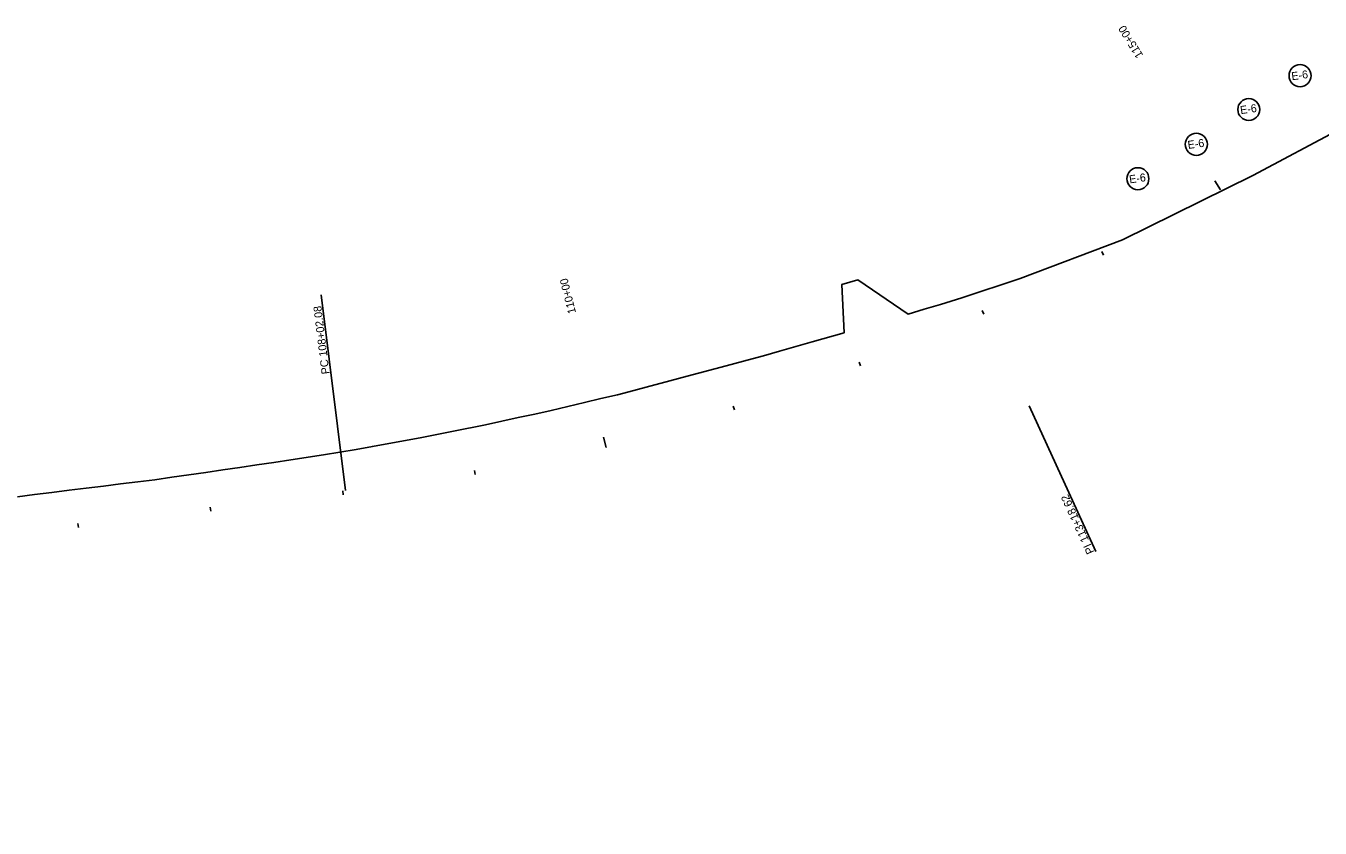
# Model space of a CAD drawing. Extents: x 1568908 to 1572777, y 730965 to 733090.
# Drawn here: x 1570843 to 1571813, y 732028 to 732629 of the extents above; entities that cross this region are included whole.
import ezdxf

# ---------------------------------------------------------------- set-up
doc = ezdxf.new("R2010")
doc.units = 0
for name, color, linetype in [('R_Erosion', 7, 'Continuous'), ('R_Horz Alg Annot', 7, 'Continuous'), ('R_No Plot', 7, 'Continuous')]:
    doc.layers.add(name, color=color, linetype=linetype)

msp = doc.modelspace()

# ---------------------------------------------------------------- linework, layer by layer
at = {"layer": 'R_Erosion'}
for centre in [(1571798.16, 732591.48), (1571759.71, 732566.13), (1571720.36, 732540.04), (1571676.53, 732514.23)]:
    msp.add_circle(centre, 8.26, dxfattribs=at)
at = {"layer": 'R_Horz Alg Annot'}
for points in [[(1571734.19, 732512.66), (1571738.37, 732505.84)], [(1571650.86, 732457.02), (1571649.45, 732459.67)], [(1571082.41, 732280.73), (1571064.28, 732427.34)], [(1571561, 732412.75), (1571559.76, 732415.48)], [(1571468.61, 732374.05), (1571467.54, 732376.85)], [(1571374.03, 732341.07), (1571373.13, 732343.93)], [(1571595.05, 732344.13), (1571644.93, 732234.99)], [(1571275.93, 732320.71), (1571277.86, 732312.94)], [(1571179.72, 732292.7), (1571179.18, 732295.65)], [(1571080.72, 732277.5), (1571080.35, 732280.48)], [(1570981.47, 732265.23), (1570981.1, 732268.21)], [(1570882.23, 732252.95), (1570881.86, 732255.93)]]:
    msp.add_lwpolyline(points, dxfattribs=at)
at = {"layer": 'R_No Plot'}
for points in [[(1572777.39, 731519.96), (1571905.83, 732616.57), (1571828.51, 732551.75), (1571762.8, 732516.69), (1571664.98, 732468.4), (1571588.26, 732439.45), (1571544.6, 732425.09)], [(1572777.39, 731519.96), (1571905.83, 732616.57), (1571828.51, 732551.75), (1571762.8, 732516.69), (1571664.98, 732468.4), (1571588.26, 732439.45), (1571544.6, 732425.09)], [(1572777.39, 731519.96), (1571905.83, 732616.57), (1571828.51, 732551.75), (1571762.8, 732516.69), (1571664.98, 732468.4), (1571588.26, 732439.45), (1571544.6, 732425.09)], [(1572777.39, 731519.96), (1571905.83, 732616.57), (1571828.51, 732551.75), (1571762.8, 732516.69), (1571664.98, 732468.4), (1571588.26, 732439.45), (1571544.6, 732425.09)], [(1571544.6, 732425.09), (1571540.52, 732423.79), (1571528.51, 732419.94), (1571516.43, 732416.4), (1571504.36, 732412.85), (1571466.64, 732438.45), (1571454.57, 732434.9), (1571456.21, 732398.85), (1571432.22, 732391.94), (1571420.08, 732388.52), (1571407.95, 732385.1), (1571395.82, 732381.68), (1571383.68, 732378.26), (1571371.49, 732375.01), (1571359.3, 732371.75), (1571347.11, 732368.49), (1571334.93, 732365.24), (1571322.8, 732362.04), (1571310.67, 732358.84), (1571298.54, 732355.64), (1571286.41, 732352.44), (1571273.98, 732349.5), (1571261.55, 732346.56), (1571249.12, 732343.61), (1571236.69, 732340.67), (1571224.35, 732337.97), (1571212.01, 732335.27), (1571199.67, 732332.57), (1571187.33, 732329.87), (1571163.51, 732325.17), (1571139.68, 732320.46), (1571127.35, 732318.19), (1571115.01, 732315.92), (1571102.68, 732313.66), (1571090.34, 732311.39), (1571065.9, 732307.45), (1571041.46, 732303.51), (1571028.73, 732301.65), (1571016, 732299.78), (1571003.27, 732297.92), (1570990.54, 732296.06), (1570977.81, 732294.23), (1570965.07, 732292.41), (1570952.33, 732290.59), (1570939.59, 732288.77), (1570926.73, 732287.18), (1570913.87, 732285.58), (1570901, 732283.99), (1570888.14, 732282.4), (1570875.22, 732280.79), (1570862.3, 732279.19), (1570849.37, 732277.58), (1570836.45, 732275.97)], [(1571544.6, 732425.09), (1571540.52, 732423.79), (1571528.51, 732419.94), (1571516.43, 732416.4), (1571504.36, 732412.85), (1571466.64, 732438.45), (1571454.57, 732434.9), (1571456.21, 732398.85), (1571432.22, 732391.94), (1571420.08, 732388.52), (1571407.95, 732385.1), (1571395.82, 732381.68), (1571383.68, 732378.26), (1571371.49, 732375.01), (1571359.3, 732371.75), (1571347.11, 732368.49), (1571334.93, 732365.24), (1571322.8, 732362.04), (1571310.67, 732358.84), (1571298.54, 732355.64), (1571286.41, 732352.44), (1571273.98, 732349.5), (1571261.55, 732346.56), (1571249.12, 732343.61), (1571236.69, 732340.67), (1571224.35, 732337.97), (1571212.01, 732335.27), (1571199.67, 732332.57), (1571187.33, 732329.87), (1571163.51, 732325.17), (1571139.68, 732320.46), (1571127.35, 732318.19), (1571115.01, 732315.92), (1571102.68, 732313.66), (1571090.34, 732311.39), (1571065.9, 732307.45), (1571041.46, 732303.51), (1571028.73, 732301.65), (1571016, 732299.78), (1571003.27, 732297.92), (1570990.54, 732296.06), (1570977.81, 732294.23), (1570965.07, 732292.41), (1570952.33, 732290.59), (1570939.59, 732288.77), (1570926.73, 732287.18), (1570913.87, 732285.58), (1570901, 732283.99), (1570888.14, 732282.4), (1570875.22, 732280.79), (1570862.3, 732279.19), (1570849.37, 732277.58), (1570836.45, 732275.97)], [(1571544.6, 732425.09), (1571540.52, 732423.79), (1571528.51, 732419.94), (1571516.43, 732416.4), (1571504.36, 732412.85), (1571466.64, 732438.45), (1571454.57, 732434.9), (1571456.21, 732398.85), (1571432.22, 732391.94), (1571420.08, 732388.52), (1571407.95, 732385.1), (1571395.82, 732381.68), (1571383.68, 732378.26), (1571371.49, 732375.01), (1571359.3, 732371.75), (1571347.11, 732368.49), (1571334.93, 732365.24), (1571322.8, 732362.04), (1571310.67, 732358.84), (1571298.54, 732355.64), (1571286.41, 732352.44), (1571273.98, 732349.5), (1571261.55, 732346.56), (1571249.12, 732343.61), (1571236.69, 732340.67), (1571224.35, 732337.97), (1571212.01, 732335.27), (1571199.67, 732332.57), (1571187.33, 732329.87), (1571163.51, 732325.17), (1571139.68, 732320.46), (1571127.35, 732318.19), (1571115.01, 732315.92), (1571102.68, 732313.66), (1571090.34, 732311.39), (1571065.9, 732307.45), (1571041.46, 732303.51), (1571028.73, 732301.65), (1571016, 732299.78), (1571003.27, 732297.92), (1570990.54, 732296.06), (1570977.81, 732294.23), (1570965.07, 732292.41), (1570952.33, 732290.59), (1570939.59, 732288.77), (1570926.73, 732287.18), (1570913.87, 732285.58), (1570901, 732283.99), (1570888.14, 732282.4), (1570875.22, 732280.79), (1570862.3, 732279.19), (1570849.37, 732277.58), (1570836.45, 732275.97)], [(1571544.6, 732425.09), (1571540.52, 732423.79), (1571528.51, 732419.94), (1571516.43, 732416.4), (1571504.36, 732412.85), (1571466.64, 732438.45), (1571454.57, 732434.9), (1571456.21, 732398.85), (1571432.22, 732391.94), (1571420.08, 732388.52), (1571407.95, 732385.1), (1571395.82, 732381.68), (1571383.68, 732378.26), (1571371.49, 732375.01), (1571359.3, 732371.75), (1571347.11, 732368.49), (1571334.93, 732365.24), (1571322.8, 732362.04), (1571310.67, 732358.84), (1571298.54, 732355.64), (1571286.41, 732352.44), (1571273.98, 732349.5), (1571261.55, 732346.56), (1571249.12, 732343.61), (1571236.69, 732340.67), (1571224.35, 732337.97), (1571212.01, 732335.27), (1571199.67, 732332.57), (1571187.33, 732329.87), (1571163.51, 732325.17), (1571139.68, 732320.46), (1571127.35, 732318.19), (1571115.01, 732315.92), (1571102.68, 732313.66), (1571090.34, 732311.39), (1571065.9, 732307.45), (1571041.46, 732303.51), (1571028.73, 732301.65), (1571016, 732299.78), (1571003.27, 732297.92), (1570990.54, 732296.06), (1570977.81, 732294.23), (1570965.07, 732292.41), (1570952.33, 732290.59), (1570939.59, 732288.77), (1570926.73, 732287.18), (1570913.87, 732285.58), (1570901, 732283.99), (1570888.14, 732282.4), (1570875.22, 732280.79), (1570862.3, 732279.19), (1570849.37, 732277.58), (1570836.45, 732275.97)]]:
    msp.add_lwpolyline(points, dxfattribs=at)

# ---------------------------------------------------------------- texts
at = {"layer": 'R_Erosion'}
for p in [(1571792.08, 732588), (1571753.63, 732562.66), (1571714.28, 732536.56), (1571670.45, 732510.76)]:
    msp.add_text('E-6 ', height=5.999, rotation=7.89288, dxfattribs=at).set_placement(p)
at = {"layer": 'R_Horz Alg Annot'}
for s, rotation, p in [('115+00', 121.47725, (1571680.73, 732606.8)), ('110+00', 103.97725, (1571255.33, 732413.92)), ('PC 108+02.08', 97.05, (1571070.59, 732368.14)), ('PI 113+18.62', 114.56247, (1571644.02, 732234.58))]:
    msp.add_text(s, height=6, rotation=rotation, dxfattribs=at).set_placement(p)

doc.saveas('drawing.dxf')
